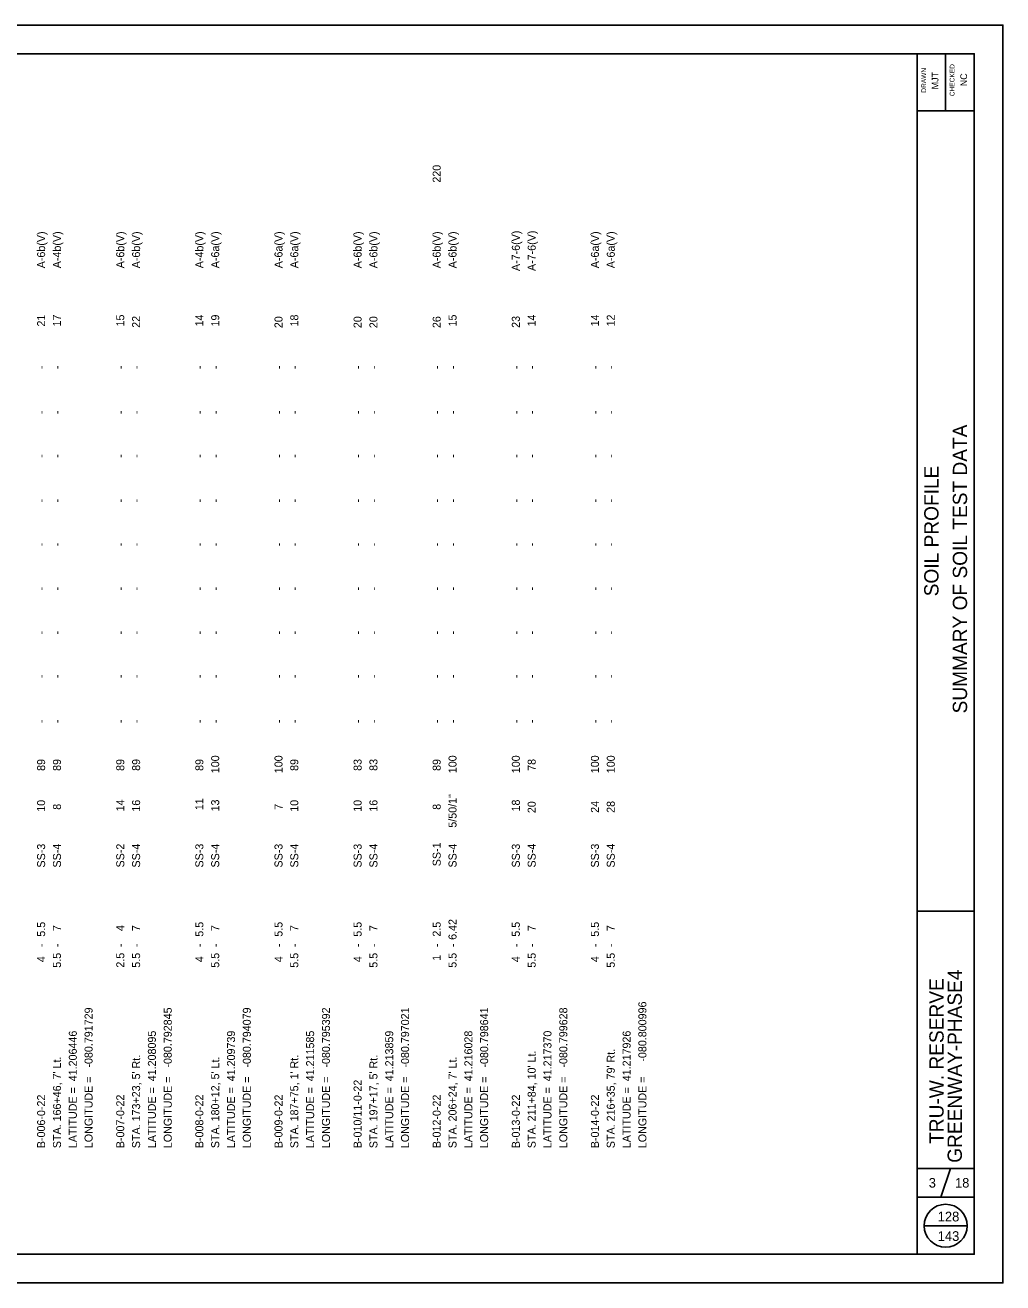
# Model space of a CAD drawing. Extents: x 0 to 83.4, y 4.5 to 46.4.
# Drawn here: x 66.31 to 83.41, y 24.4 to 46.4 of the extents above; entities that cross this region are included whole.
import ezdxf

# ---------------------------------------------------------------- set-up
doc = ezdxf.new("R2010")
doc.units = 0
for name, color, linetype in [('SH_Border', 7, 'Continuous'), ('SH_Cut_Line', 7, 'Continuous'), ('SH_Data', 7, 'Continuous'), ('TX_P_1', 7, 'Continuous')]:
    doc.layers.add(name, color=color, linetype=linetype)

msp = doc.modelspace()

# ---------------------------------------------------------------- linework, layer by layer
at = {"layer": 'SH_Border'}
for p, q in [((81.906, 24.904), (81.906, 45.904)), ((82.406, 44.904), (82.406, 45.904)), ((81.906, 44.904), (82.906, 44.904)), ((81.906, 30.904), (82.906, 30.904)), ((81.906, 26.404), (82.906, 26.404)), ((82.323, 25.904), (82.489, 26.404)), ((81.906, 25.904), (82.906, 25.904))]:
    msp.add_line(p, q, dxfattribs=at)
msp.add_lwpolyline([(51.406, 45.904), (82.906, 45.904), (82.906, 24.904), (51.406, 24.904)], close=True, dxfattribs=at)
at = {"layer": 'SH_Cut_Line'}
msp.add_lwpolyline([(49.406, 24.404), (83.406, 24.404), (83.406, 46.404), (49.406, 46.404)], close=True, dxfattribs=at)
at = {"layer": 'SH_Data'}
msp.add_line((82.031, 25.404), (82.781, 25.404), dxfattribs=at)
msp.add_circle((82.406, 25.404), 0.375, dxfattribs=at)

# ---------------------------------------------------------------- texts
for s, height, p in [('DRAWN', 0.0833, (82.064, 45.222)), ('MJT', 0.1167, (82.28, 45.281)), ('CHECKED', 0.0833, (82.56, 45.161)), ('NC', 0.1167, (82.78, 45.336)), ('SUMMARY OF SOIL TEST DATA', 0.25, (82.781, 34.365)), ('SOIL PROFILE', 0.25, (82.281, 36.413)), ('TRU-W. RESERVE', 0.25, (82.371, 26.835)), ('GREENWAY-PHASE4', 0.25, (82.69, 26.504))]:
    msp.add_text(s, height=height, rotation=90, dxfattribs=at).set_placement(p)
for s, height, p in [('3', 0.167, (82.111, 26.071)), ('18', 0.1666, (82.572, 26.071)), ('128', 0.17, (82.266, 25.479)), ('143', 0.17, (82.266, 25.137))]:
    msp.add_text(s, height=height, dxfattribs=at).set_placement(p)
at = {"layer": 'TX_P_1'}
for s, p in [('220', (73.576, 43.649)), ('A-6b(V)', (66.659, 42.151)), ('A-4b(V)', (66.936, 42.152)), ('A-6b(V)', (68.043, 42.151)), ('A-6b(V)', (68.32, 42.151)), ('A-4b(V)', (69.426, 42.152)), ('A-6a(V)', (69.703, 42.152)), ('A-6a(V)', (70.81, 42.152)), ('A-6a(V)', (71.086, 42.152)), ('A-6b(V)', (72.193, 42.151)), ('A-6b(V)', (72.47, 42.151)), ('A-6b(V)', (73.576, 42.151)), ('A-6b(V)', (73.853, 42.151)), ('A-7-6(V)', (74.96, 42.103)), ('A-7-6(V)', (75.237, 42.103)), ('A-6a(V)', (76.343, 42.152)), ('A-6a(V)', (76.62, 42.152)), ('21', (66.659, 41.132)), ('17', (66.936, 41.133)), ('15', (68.043, 41.133)), ('22', (68.32, 41.11)), ('14', (69.426, 41.134)), ('19', (69.703, 41.133)), ('20', (70.81, 41.104)), ('18', (71.086, 41.133)), ('20', (72.193, 41.104)), ('20', (72.47, 41.104)), ('26', (73.576, 41.105)), ('15', (73.853, 41.133)), ('23', (74.96, 41.109)), ('14', (75.237, 41.134)), ('14', (76.343, 41.134)), ('12', (76.62, 41.134)), ('-', (66.659, 40.389)), ('-', (66.936, 40.389)), ('-', (68.043, 40.389)), ('-', (68.32, 40.389)), ('-', (69.426, 40.389)), ('-', (69.703, 40.389)), ('-', (70.81, 40.389)), ('-', (71.086, 40.389)), ('-', (72.193, 40.389)), ('-', (72.47, 40.389)), ('-', (73.576, 40.389)), ('-', (73.853, 40.389)), ('-', (74.96, 40.389)), ('-', (75.237, 40.389)), ('-', (76.343, 40.389)), ('-', (76.62, 40.389)), ('-', (66.659, 39.6)), ('-', (66.936, 39.6)), ('-', (68.043, 39.6)), ('-', (68.32, 39.6)), ('-', (69.426, 39.6)), ('-', (69.703, 39.6)), ('-', (70.81, 39.6)), ('-', (71.086, 39.6)), ('-', (72.193, 39.6)), ('-', (72.47, 39.6)), ('-', (73.576, 39.6)), ('-', (73.853, 39.6)), ('-', (74.96, 39.6)), ('-', (75.237, 39.6)), ('-', (76.343, 39.6)), ('-', (76.62, 39.6)), ('-', (66.659, 38.838)), ('-', (66.936, 38.838)), ('-', (68.043, 38.838)), ('-', (68.32, 38.838)), ('-', (69.426, 38.838)), ('-', (69.703, 38.838)), ('-', (70.81, 38.838)), ('-', (71.086, 38.838)), ('-', (72.193, 38.838)), ('-', (72.47, 38.838)), ('-', (73.576, 38.838)), ('-', (73.853, 38.838)), ('-', (74.96, 38.838)), ('-', (75.237, 38.838)), ('-', (76.343, 38.838)), ('-', (76.62, 38.838)), ('-', (66.659, 38.053)), ('-', (66.936, 38.053)), ('-', (68.043, 38.053)), ('-', (68.32, 38.053)), ('-', (69.426, 38.053)), ('-', (69.703, 38.053)), ('-', (70.81, 38.053)), ('-', (71.086, 38.053)), ('-', (72.193, 38.053)), ('-', (72.47, 38.053)), ('-', (73.576, 38.053)), ('-', (73.853, 38.053)), ('-', (74.96, 38.053)), ('-', (75.237, 38.053)), ('-', (76.343, 38.053)), ('-', (76.62, 38.053)), ('-', (66.659, 37.288)), ('-', (66.936, 37.288)), ('-', (68.043, 37.288)), ('-', (68.32, 37.288)), ('-', (69.426, 37.288)), ('-', (69.703, 37.288)), ('-', (70.81, 37.288)), ('-', (71.086, 37.288)), ('-', (72.193, 37.288)), ('-', (72.47, 37.288)), ('-', (73.576, 37.288)), ('-', (73.853, 37.288)), ('-', (74.96, 37.288)), ('-', (75.237, 37.288)), ('-', (76.343, 37.288)), ('-', (76.62, 37.288)), ('-', (66.659, 36.514)), ('-', (66.936, 36.514)), ('-', (68.043, 36.514)), ('-', (68.32, 36.514)), ('-', (69.426, 36.514)), ('-', (69.703, 36.514)), ('-', (70.81, 36.514)), ('-', (71.086, 36.514)), ('-', (72.193, 36.514)), ('-', (72.47, 36.514)), ('-', (73.576, 36.514)), ('-', (73.853, 36.514)), ('-', (74.96, 36.514)), ('-', (75.237, 36.514)), ('-', (76.343, 36.514)), ('-', (76.62, 36.514)), ('-', (66.659, 35.744)), ('-', (66.936, 35.744)), ('-', (68.043, 35.744)), ('-', (68.32, 35.744)), ('-', (69.426, 35.744)), ('-', (69.703, 35.744)), ('-', (70.81, 35.744)), ('-', (71.086, 35.744)), ('-', (72.193, 35.744)), ('-', (72.47, 35.744)), ('-', (73.576, 35.744)), ('-', (73.853, 35.744)), ('-', (74.96, 35.744)), ('-', (75.237, 35.744)), ('-', (76.343, 35.744)), ('-', (76.62, 35.744)), ('-', (66.659, 34.984)), ('-', (66.936, 34.984)), ('-', (68.043, 34.984)), ('-', (68.32, 34.984)), ('-', (69.426, 34.984)), ('-', (69.703, 34.984)), ('-', (70.81, 34.984)), ('-', (71.086, 34.984)), ('-', (72.193, 34.984)), ('-', (72.47, 34.984)), ('-', (73.576, 34.984)), ('-', (73.853, 34.984)), ('-', (74.96, 34.984)), ('-', (75.237, 34.984)), ('-', (76.343, 34.984)), ('-', (76.62, 34.984)), ('-', (66.659, 34.193)), ('-', (66.936, 34.193)), ('-', (68.043, 34.193)), ('-', (68.32, 34.193)), ('-', (69.426, 34.193)), ('-', (69.703, 34.193)), ('-', (70.81, 34.193)), ('-', (71.086, 34.193)), ('-', (72.193, 34.193)), ('-', (72.47, 34.193)), ('-', (73.576, 34.193)), ('-', (73.853, 34.193)), ('-', (74.96, 34.193)), ('-', (75.237, 34.193)), ('-', (76.343, 34.193)), ('-', (76.62, 34.193)), ('89', (66.659, 33.359)), ('89', (66.936, 33.359)), ('89', (68.043, 33.359)), ('89', (68.32, 33.36)), ('89', (69.426, 33.359)), ('100', (69.703, 33.319)), ('100', (70.81, 33.319)), ('89', (71.086, 33.359)), ('83', (72.193, 33.36)), ('83', (72.47, 33.36)), ('89', (73.576, 33.359)), ('100', (73.853, 33.319)), ('100', (74.96, 33.319)), ('78', (75.237, 33.36)), ('100', (76.343, 33.319)), ('100', (76.62, 33.319)), ('10', (66.659, 32.644)), ('14', (68.043, 32.651)), ('16', (68.32, 32.646)), ('11', (69.426, 32.672)), ('13', (69.703, 32.65)), ('10', (71.086, 32.644)), ('10', (72.193, 32.644)), ('16', (72.47, 32.646)), ('5/50/1"', (73.853, 32.366)), ('18', (74.96, 32.649)), ('20', (75.237, 32.62)), ('24', (76.343, 32.626)), ('28', (76.62, 32.625)), ('8', (66.936, 32.679)), ('7', (70.81, 32.679)), ('8', (73.576, 32.679)), ('SS-3', (66.659, 31.669)), ('SS-4', (66.936, 31.669)), ('SS-2', (68.043, 31.67)), ('SS-4', (68.32, 31.669)), ('SS-3', (69.426, 31.669)), ('SS-4', (69.703, 31.669)), ('SS-3', (70.81, 31.669)), ('SS-4', (71.086, 31.669)), ('SS-3', (72.193, 31.668)), ('SS-4', (72.47, 31.669)), ('SS-1', (73.576, 31.692)), ('SS-4', (73.853, 31.669)), ('SS-3', (74.96, 31.669)), ('SS-4', (75.237, 31.669)), ('SS-3', (76.343, 31.669)), ('SS-4', (76.62, 31.669)), ('5.5', (66.659, 30.459)), ('7', (66.936, 30.556)), ('4', (68.043, 30.557)), ('7', (68.32, 30.556)), ('5.5', (69.426, 30.459)), ('7', (69.703, 30.556)), ('5.5', (70.81, 30.459)), ('7', (71.086, 30.556)), ('5.5', (72.193, 30.459)), ('7', (72.47, 30.556)), ('2.5', (73.576, 30.46)), ('6.42', (73.853, 30.404)), ('5.5', (74.96, 30.459)), ('7', (75.237, 30.556)), ('5.5', (76.343, 30.459)), ('7', (76.62, 30.556)), ('-', (66.659, 30.276)), ('5.5', (66.936, 29.916)), ('-', (66.936, 30.276)), ('2.5', (68.043, 29.918)), ('-', (68.043, 30.276)), ('5.5', (68.32, 29.916)), ('-', (68.32, 30.276)), ('-', (69.426, 30.276)), ('5.5', (69.703, 29.916)), ('-', (69.703, 30.276)), ('-', (70.81, 30.276)), ('5.5', (71.086, 29.916)), ('-', (71.086, 30.276)), ('-', (72.193, 30.276)), ('5.5', (72.47, 29.916)), ('-', (72.47, 30.276)), ('-', (73.576, 30.276)), ('5.5', (73.853, 29.916)), ('-', (73.853, 30.276)), ('-', (74.96, 30.276)), ('5.5', (75.237, 29.916)), ('-', (75.237, 30.276)), ('-', (76.343, 30.276)), ('5.5', (76.62, 29.916)), ('-', (76.62, 30.276)), ('4', (66.659, 30.014)), ('4', (69.426, 30.014)), ('4', (70.81, 30.014)), ('4', (72.193, 30.014)), ('1', (73.576, 30.037)), ('4', (74.96, 30.014)), ('4', (76.343, 30.014)), ('LONGITUDE =     -080.800996', (77.173, 26.76)), ('LONGITUDE =   -080.791729', (67.489, 26.76)), ('LONGITUDE =   -080.792845', (68.873, 26.76)), ('LONGITUDE =   -080.794079', (70.256, 26.76)), ('LONGITUDE =   -080.795392', (71.64, 26.76)), ('LONGITUDE =   -080.797021', (73.023, 26.76)), ('LONGITUDE =   -080.798641', (74.406, 26.76)), ('LONGITUDE =   -080.799628', (75.79, 26.76)), ('LATITUDE =  41.206446', (67.213, 26.76)), ('LATITUDE =  41.208095', (68.596, 26.76)), ('LATITUDE =  41.209739', (69.98, 26.76)), ('LATITUDE =  41.211585', (71.363, 26.76)), ('LATITUDE =  41.213859', (72.746, 26.76)), ('LATITUDE =  41.216028', (74.13, 26.76)), ('LATITUDE =  41.217370', (75.513, 26.76)), ('LATITUDE =  41.217926', (76.897, 26.76)), ("STA. 211+84, 10' Lt.", (75.237, 26.76)), ("STA. 216+35, 79' Rt.", (76.62, 26.76)), ("STA. 166+46, 7' Lt.", (66.936, 26.76)), ("STA. 173+23, 5' Rt.", (68.32, 26.76)), ("STA. 180+12, 5' Lt.", (69.703, 26.76)), ("STA. 187+75, 1' Rt.", (71.086, 26.76)), ("STA. 197+17, 5' Rt.", (72.47, 26.76)), ("STA. 206+24, 7' Lt.", (73.853, 26.76)), ('B-010/11-0-22', (72.193, 26.76)), ('B-006-0-22', (66.659, 26.76)), ('B-007-0-22', (68.043, 26.76)), ('B-008-0-22', (69.426, 26.76)), ('B-009-0-22', (70.81, 26.76)), ('B-012-0-22', (73.576, 26.76)), ('B-013-0-22', (74.96, 26.76)), ('B-014-0-22', (76.343, 26.76))]:
    msp.add_text(s, height=0.14, rotation=90, dxfattribs=at).set_placement(p)

doc.saveas('drawing.dxf')
